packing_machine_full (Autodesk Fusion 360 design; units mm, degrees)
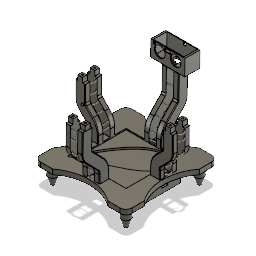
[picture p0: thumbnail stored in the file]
sketch "Sketch1" plane through (0, 0, 0) normal (0, 1, 0) x axis (1, 0, 0)
  line L1 (31.4678, 7.6066) -> (-53.5322, 7.6066)
  line L2 (-53.5322, -77.3934) -> (31.4678, -77.3934)
  line L3 (-53.5322, 7.6066) -> (-53.5322, -77.3934)
  line L4 (-24.0269, 7.6066) -> (-16.0269, 7.6066)
  line L5 (-24.0269, 23.3155) -> (-24.0269, 7.6066)
  line L6 (-16.0269, 7.6066) -> (-16.0269, 23.3155)
  line L7 (3.9731, 7.6066) -> (-4.0269, 7.6066)
  line L8 (3.9731, 23.3155) -> (3.9731, 7.6066)
  line L9 (-4.0269, 7.6066) -> (-4.0269, 23.3155)
  line L10 (-69.5322, -10.1974) -> (-53.5322, -10.1974)
  line L11 (-53.5322, -18.1974) -> (-69.5322, -18.1974)
  line L12 (-53.5322, -10.1974) -> (-53.5322, -18.1974)
  line L13 (-69.5322, -30.1974) -> (-53.5322, -30.1974)
  line L14 (-53.5322, -38.1974) -> (-69.5322, -38.1974)
  line L15 (-53.5322, -30.1974) -> (-53.5322, -38.1974)
  line L16 (-24.0269, -93.3934) -> (-24.0269, -77.3934)
  line L17 (-16.0269, -93.3934) -> (-16.0269, -77.3934)
  line L18 (-4.0269, -93.3934) -> (-4.0269, -77.3934)
  line L19 (3.9731, -93.3934) -> (3.9731, -77.3934)
  line L20 (31.4678, -77.3934) -> (31.4678, 7.6066)
  line L21 (47.4678, -18.1974) -> (31.4678, -18.1974)
  line L22 (47.4678, -10.1974) -> (31.4678, -10.1974)
  line L23 (47.4678, -30.1974) -> (31.4678, -30.1974)
  line L24 (47.4678, -38.1974) -> (31.4678, -38.1974)
  line L25 (-59.6337, -72.3934) -> (-62.6337, -72.3934)
  line L26 (37.4678, -72.3934) -> (40.4678, -72.3934)
  line L27 (-59.6337, 2.6066) -> (-62.6337, 2.6066)
  line L28 (37.4678, 2.6066) -> (40.4678, 2.6066)
  line L29 (-59.6337, -72.3934) -> (-59.6337, 2.6066)
  line L30 (37.4678, 2.6066) -> (37.4678, -72.3934)
  line L31 (-62.6337, -72.3934) -> (-62.6337, 2.6066)
  line L32 (40.4678, -72.3934) -> (40.4678, 2.6066)
  line L33 (-69.5322, -18.1974) -> (-69.5322, -10.1974)
  line L34 (-69.5322, -38.1974) -> (-69.5322, -30.1974)
  line L35 (47.4678, -18.1974) -> (47.4678, -10.1974)
  line L36 (47.4678, -38.1974) -> (47.4678, -30.1974)
  line L37 (-16.0269, -93.3934) -> (-24.0269, -93.3934)
  line L38 (3.9731, -93.3934) -> (-4.0269, -93.3934)
  line L39 (-4.0269, 23.3155) -> (3.9731, 23.3155)
  line L40 (-24.0269, 23.3155) -> (-16.0269, 23.3155)
  line L41 (-5, -80) -> (-15, -80)
  line L42 (-5, -85) -> (-5, -80)
  line L43 (-15, -85) -> (-5, -85)
  line L44 (-15, -80) -> (-15, -85)
  line L45 (-5, 10) -> (-15, 10)
  line L46 (-5, 15) -> (-5, 10)
  line L47 (-15, 15) -> (-5, 15)
  line L48 (-15, 10) -> (-15, 15)
  line L49 (-64, -19) -> (-69, -19)
  line L50 (-64, -29) -> (-64, -19)
  line L51 (-69, -29) -> (-64, -29)
  line L52 (-69, -19) -> (-69, -29)
  line L53 (46.4751, -19) -> (41.4751, -19)
  line L54 (46.4751, -29) -> (46.4751, -19)
  line L55 (41.4751, -29) -> (46.4751, -29)
  line L56 (41.4751, -19) -> (41.4751, -29)
  line L57 (63.9678, 9.8155) -> (63.9678, 30.1039)
  line L58 (-86.0322, -99.8934) -> (-86.0322, -79.8934)
  line L59 (63.9678, -79.8934) -> (63.9678, -99.8934)
  line L60 (53.9678, -109.8934) -> (33.9678, -109.8934)
  line L61 (-76.0322, -109.8934) -> (-56.0322, -109.8934)
  line L62 (-86.0322, 10.1066) -> (-86.0322, 30.1026)
  line L63 (53.9691, 40.1039) -> (33.9678, 40.1066)
  line L64 (-76.0322, 40.1026) -> (-56.0322, 40.1026)
  curve K1 (-62.3587, -78.4407) -> (-62.3587, -78.4407)
  circle C1 centre (48.9678, 24.8155) radius 7.5
  circle C2 centre (-71.0322, 25.1066) radius 7.5
  circle C3 centre (-71.0322, -94.8934) radius 7.5
  circle C4 centre (48.9678, -94.8934) radius 7.5
  arc A1 centre (-11.0349, 100.0947) radius 74.9921 clockwise from (33.9678, 40.1066) to (-56.0322, 40.1026)
  arc A2 centre (123.5319, -35.039) radius 74.5641 clockwise from (63.9678, -79.8934) to (63.9678, 9.8155)
  arc A3 centre (-11.0322, -169.8934) radius 75 clockwise from (-56.0322, -109.8934) to (33.9678, -109.8934)
  arc A4 centre (-146.0322, -34.8934) radius 75 clockwise from (-86.0322, 10.1066) to (-86.0322, -79.8934)
  arc A5 centre (-76.0322, 30.1026) radius 10 clockwise from (-86.0322, 30.1026) to (-76.0322, 40.1026)
  arc A6 centre (53.9678, 30.1039) radius 10 clockwise from (53.9691, 40.1039) to (63.9678, 30.1039)
  arc A7 centre (53.9678, -99.8934) radius 10 clockwise from (63.9678, -99.8934) to (53.9678, -109.8934)
  arc A8 centre (-76.0322, -99.8934) radius 10 clockwise from (-76.0322, -109.8934) to (-86.0322, -99.8934)
  point P4 (-53.5322, -77.3934)
  point P5 (-53.5322, 7.6066)
  point P28 (-62.6337, -72.3934)
  point P29 (-59.6337, -72.3934)
  point P30 (40.4678, -72.3934)
  point P31 (37.4678, -72.3934)
  point P32 (-62.6337, 2.6066)
  point P33 (-59.6337, 2.6066)
  point P34 (40.4678, 2.6066)
  point P35 (37.4678, 2.6066)
  point P52 (-15, -80)
  point P53 (-5, -80)
  point P55 (-15, -85)
  point P56 (-15, 10)
  point P57 (-5, 10)
  point P59 (-15, 15)
  point P60 (-69, -19)
  point P61 (-64, -19)
  point P63 (-69, -29)
  point P64 (41.4751, -19)
  point P65 (46.4751, -19)
  point P67 (41.4751, -29)
  dimension "d121" diameter C1 = 15
  dimension "d124" diameter C2 = 15
  dimension "d127" diameter C3 = 15
  dimension "d130" diameter C4 = 15
  dimension "d162" distance P4 P5 = 85
  dimension "d167" distance L6 L9 = 12
  dimension "d169" distance L11 L13 = 12
  dimension "d179" distance P28 P29 = 3
  dimension "d181" distance P30 P31 = 3
  dimension "d183" distance P32 P33 = 3
  dimension "d186" distance P34 P35 = 3
  dimension "d188" distance L2 L25 = 5
  dimension "d189" distance L2 L26 = 5
  dimension "d192" distance L1 L28 = 5
  dimension "d193" distance L1 L27 = 5
  dimension "d407" distance P52 P53 = 10
  dimension "d408" distance P52 P55 = 5
  dimension "d409" distance P56 P57 = 10
  dimension "d410" distance P56 P59 = 5
  dimension "d411" distance P60 P61 = 5
  dimension "d412" distance P60 P63 = 10
  dimension "d413" distance P64 P65 = 5
  dimension "d414" distance P64 P67 = 10
  dimension "d502" radius A5 = 10
extrude "Extrude26" new body sketch "Sketch1" profile of L3 L25 L29 K1 along normal blind 3
extrude "Extrude9" new body sketch "Sketch1" profile of C1 C2 C3 C4 against normal blind 15
extrude "Extrude2" new body sketch "Sketch1" profile of L1 L2 L3 L4 L7 L12 L15 L20 K1 along normal blind 6
extrude "Extrude1" new body sketch "Sketch1" profile of L1 L2 L3 L4 L5 L6 L7 L8 L9 L10 L11 L12 L13 L14 L15 C1 C2 C3 C4 L16 L17 L18 L19 L20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 along normal blind 8
sketch "Sketch3" plane through (0, 0, 0) normal (1, 0, 0) x axis (0, 0, -1)
  line L1 (-77.6845, 0) -> (-89.6845, 0)
  line L2 (-81.7624, 30.5676) -> (-81.7624, 0.5676)
  line L3 (-109.6726, 59.221) -> (-81.7624, 30.5676)
  line L4 (-109.0151, 94.2149) -> (-109.6726, 59.221)
  line L5 (23.3155, 0) -> (7.6066, 0)
  line L6 (10, 30.5) -> (10, 0.5)
  line L7 (37.7935, 59.2667) -> (10, 30.5)
  line L8 (38.6405, 99.2577) -> (37.7935, 59.2667)
  point P4 (-81.7624, 0.5676)
  point P5 (-81.7624, 30.5676)
  point P6 (-109.6726, 59.221)
  point P7 (-109.0151, 94.2149)
  point P10 (10, 0.5)
  point P11 (10, 30.5)
  point P12 (37.7935, 59.2667)
  point P13 (38.6405, 99.2577)
  dimension "d21" distance P4 P5 = 30
  dimension "d23" distance P5 P6 = 40
  dimension "d24" distance P6 P7 = 35
  dimension "d26" distance P10 P11 = 30
  dimension "d28" distance P11 P12 = 40
  dimension "d29" distance P12 P13 = 40
sweep "Sweep2" sketch "Sketch1" TwistAngle 0 TaperAngle 0
sweep "Sweep1" sketch "Sketch1" TwistAngle 0 TaperAngle 0
sketch "Sketch4"
  line L1 (31.4678, 0) -> (43.352, 0)
  line L2 (34, 31) -> (34, 1)
  line L3 (55.2132, 52.2132) -> (34, 31)
  line L4 (55.2132, 82.2132) -> (55.2132, 52.2132)
  line L5 (-56.9466, 31) -> (-56.9466, 1)
  line L6 (-78.1598, 52.2132) -> (-56.9466, 31)
  line L7 (-78.1598, 82.2132) -> (-78.1598, 52.2132)
  point P4 (34, 1)
  point P5 (34, 31)
  point P6 (55.2132, 52.2132)
  point P7 (55.2132, 82.2132)
  point P10 (-78.1598, 52.2132)
  point P11 (-78.1598, 82.2132)
  dimension "d42" distance P4 P5 = 30
  dimension "d44" distance P5 P6 = 30
  dimension "d45" distance P6 P7 = 30
  dimension "d415" distance P10 P11 = 30
sweep "Sweep3" sketch "Sketch1" TwistAngle 0 TaperAngle 0
sweep "Sweep4" sketch "Sketch1" TwistAngle 0 TaperAngle 0
fillet "Fillet1" radius 1
work_plane "WorkPlane1" AlongDistance 15
sketch "Sketch8" plane through (-71.0322, -30, -24.8155) normal (0, -1, 0) x axis (1, 0, 0)
  circle C1 centre (0, 0) radius 2.5
  dimension "d136" diameter C1 = 5
loft "Loft1" sketch "Sketch8"
work_plane "WorkPlane2" AlongDistance 15
sketch "Sketch9" plane through (-71.0322, -30, 95.1845) normal (0, -1, 0) x axis (1, 0, 0)
  circle C1 centre (0, 0) radius 2.5
  dimension "d138" diameter C1 = 5
loft "Loft2" sketch "Sketch9"
work_plane "WorkPlane3" AlongDistance 15
sketch "Sketch10" plane through (48.9678, -30, -24.8155) normal (0, -1, 0) x axis (1, 0, 0)
  circle C1 centre (0, 0) radius 2.5
  dimension "d140" diameter C1 = 5
loft "Loft3" sketch "Sketch10"
work_plane "WorkPlane4" AlongDistance 15
sketch "Sketch11" plane through (48.9678, -30, 95.1845) normal (0, -1, 0) x axis (1, 0, 0)
  circle C1 centre (0, 0) radius 2.5
  dimension "d142" diameter C1 = 5
loft "Loft4" sketch "Sketch11"
fillet "Fillet5" radius 3
sketch "Sketch12" plane through (0, 0, 18.1974) normal (0, 0, 1) x axis (1, 0, 0)
  line L1 (-53.5322, 0) -> (-69.5322, 0)
  line L2 (-90.7454, 82.2132) -> (-74.7454, 82.2132)
  line L3 (-53.5322, 32.4143) -> (-53.5322, 0)
  line L4 (-74.7454, 53.6275) -> (-53.5322, 32.4143)
  line L5 (-74.7454, 82.2132) -> (-74.7454, 53.6275)
  line L6 (-90.7454, 47.0001) -> (-90.7454, 82.2132)
  line L7 (-69.5322, 25.7869) -> (-90.7454, 47.0001)
  line L8 (-69.5322, 0) -> (-69.5322, 25.7869)
extrude "Extrude10" add of existing geometry blind 5
sketch "Sketch13" plane through (0, 0, 0) normal (0, 1, 0) x axis (1, 0, 0)
extrude "Extrude11" add sketch "Sketch1" profile of L25 L26 L27 L28 against normal blind 20
sketch "Sketch18" plane through (0, 0, 18.1974) normal (0, 0, 1) x axis (1, 0, 0)
  line L1 (-90.7454, 47.0001) -> (-90.7454, 82.2132)
  line L2 (68.681, 47.0001) -> (68.681, 92.2132)
  circle C1 centre (-89.7454, 79) radius 1
  circle C2 centre (-75.7454, 79) radius 1
  circle C3 centre (-89.7454, 63.5) radius 1
  circle C4 centre (-75.7454, 63.5) radius 1
  circle C5 centre (-87.8667, 48.3965) radius 1
  circle C6 centre (-73.032, 49.7524) radius 1
  circle C7 centre (-65.5074, 41.1094) radius 1
  circle C8 centre (-56.2089, 29.9048) radius 1
  circle C9 centre (-54.7124, 23.0048) radius 1
  circle C10 centre (-54.765, 11.5923) radius 1
  circle C11 centre (-68.3402, 11.4595) radius 1
  circle C12 centre (-68, 23) radius 1
  circle C13 centre (-70, 29) radius 1
  circle C14 centre (-81, 40) radius 1
  circle C15 centre (-89.7454, 79) radius 1
  circle C16 centre (-75.7454, 79) radius 1
  circle C17 centre (-89.7454, 63.5) radius 1
  circle C18 centre (-75.7454, 63.5) radius 1
  circle C19 centre (-81, 40) radius 1
  circle C20 centre (-87.8667, 48.3965) radius 1
  circle C21 centre (-70, 29) radius 1
  circle C22 centre (-68, 23) radius 1
  circle C23 centre (-54.7124, 23.0048) radius 1
  circle C24 centre (-56.2089, 29.9048) radius 1
  circle C25 centre (-65.5074, 41.1094) radius 1
  circle C26 centre (-68.3402, 11.4595) radius 1
  circle C27 centre (-54.765, 11.5923) radius 1
  circle C28 centre (67.681, 69.5) radius 1
  circle C29 centre (53.681, 79) radius 1
  circle C30 centre (53.681, 69.5) radius 1
  circle C31 centre (53.681, 69.5) radius 1
  circle C32 centre (67.681, 69.5) radius 1
  circle C33 centre (67.681, 79) radius 1
  circle C34 centre (46.2758, 11.4595) radius 1
  circle C35 centre (46.2758, 11.4595) radius 1
  circle C36 centre (32.7006, 11.5923) radius 1
  circle C37 centre (32.7006, 11.5923) radius 1
  circle C38 centre (34.1444, 29.9048) radius 1
  circle C39 centre (43.4429, 41.1094) radius 1
  circle C40 centre (43.4429, 41.1094) radius 1
  circle C41 centre (47.9356, 29) radius 1
  circle C42 centre (58.9356, 40) radius 1
  circle C43 centre (47.9356, 29) radius 1
  circle C44 centre (65.8022, 48.3965) radius 1
  circle C45 centre (45.9356, 23) radius 1
  circle C46 centre (65.8022, 48.3965) radius 1
  circle C47 centre (32.648, 23.0048) radius 1
  circle C48 centre (50.9676, 49.7524) radius 1
  circle C49 centre (32.648, 23.0048) radius 1
  circle C50 centre (34.1444, 29.9048) radius 1
  circle C51 centre (67.681, 79) radius 1
  circle C52 centre (45.9356, 23) radius 1
  circle C53 centre (58.9356, 40) radius 1
  point P4 (-89.7454, 79)
  dimension "d269" diameter C1 = 2
  dimension "d270" distance L1 P4 = 1
  dimension "d275" diameter C7 = 2
  dimension "d276" diameter C8 = 2
  dimension "d277" diameter C9 = 2
  dimension "d278" diameter C10 = 2
  dimension "d279" diameter C14 = 2
  dimension "d280" diameter C13 = 2
  dimension "d281" diameter C12 = 2
  dimension "d282" diameter C11 = 2
  dimension "d305" diameter C15 = 2
  dimension "d306" diameter C25 = 2
  dimension "d307" diameter C24 = 2
  dimension "d308" diameter C23 = 2
  dimension "d309" diameter C27 = 2
  dimension "d310" diameter C19 = 2
  dimension "d311" diameter C21 = 2
  dimension "d312" diameter C22 = 2
  dimension "d313" diameter C26 = 2
sketch "Sketch19" plane through (37.4678, 0, 0) normal (-1, 0, 0) x axis (0, 0, 1)
  line L1 (-2.6066, 0) -> (72.3934, 0)
  line L2 (-2.6066, -20) -> (-2.6066, 0)
  line L3 (72.3934, -20) -> (-2.6066, -20)
  line L4 (72.3934, 0) -> (72.3934, -20)
  line L5 (-2.6066, -20) -> (72.3934, -20)
  line L6 (-2.6066, -17) -> (-2.6066, -20)
  line L7 (72.3934, -17) -> (-2.6066, -17)
  line L8 (72.3934, -20) -> (72.3934, -17)
  line L9 (0.3934, -17) -> (-2.6066, -17)
  line L10 (0.3934, -14) -> (0.3934, -17)
  line L11 (-2.6066, -14) -> (0.3934, -14)
  line L12 (-2.6066, -17) -> (-2.6066, -14)
  point P6 (72.3934, -20)
  point P9 (72.3934, -17)
  point P8 (-2.6066, -17)
  point P12 (-2.6066, -14)
  point P10 (0.3934, -17)
  dimension "d255" distance P6 P9 = 3
  dimension "d258" distance P8 P12 = 3
  dimension "d259" distance P8 P10 = 3
extrude "Extrude18" add sketch "Sketch19" profile of L2 L3 L4 along normal blind 5
sketch "Sketch20" plane through (-59.6337, 0, 0) normal (1, 0, 0) x axis (0, 0, -1)
  line L1 (-72.3934, 0) -> (2.6066, 0)
  line L2 (-72.3934, -20) -> (-72.3934, 0)
  line L3 (2.6066, -20) -> (-72.3934, -20)
  line L4 (2.6066, 0) -> (2.6066, -20)
  line L5 (2.6066, -20) -> (-72.3934, -20)
  line L6 (2.6066, -17) -> (2.6066, -20)
  line L7 (-72.3934, -17) -> (2.6066, -17)
  line L8 (-72.3934, -20) -> (-72.3934, -17)
  line L9 (-0.3934, -17) -> (2.6066, -17)
  line L10 (-0.3934, -14) -> (-0.3934, -17)
  line L11 (2.6066, -14) -> (-0.3934, -14)
  line L12 (2.6066, -17) -> (2.6066, -14)
  point P6 (-72.3934, -20)
  point P7 (2.6066, -20)
  point P9 (-72.3934, -17)
  point P8 (2.6066, -17)
  point P10 (-0.3934, -17)
  point P12 (2.6066, -14)
  dimension "d227" distance P6 P7 = 75
  dimension "d228" distance P6 P9 = 3
  dimension "d229" distance P8 P10 = 3
  dimension "d230" distance P8 P12 = 3
extrude "Extrude19" add sketch "Sketch20" profile of L2 L3 L4 L5 L6 L7 L8 L9 L10 L11 L12 along normal blind 5
combine "Combine1"
fillet "Fillet13" radius 12
fillet "Fillet14" radius 30
fillet "Fillet15" radius 5
fillet "Fillet16" radius 20
sketch "Sketch21" plane through (0, 82.2132, 0) normal (0, 1, 0) x axis (-1, 0, 0)
  line L1 (89.7454, 10.1974) -> (75.7454, 10.1974)
  line L2 (90.7454, 18.1974) -> (90.7454, 11.1974)
  line L3 (74.7454, 18.1974) -> (90.7454, 18.1974)
  line L4 (74.7454, 11.1974) -> (74.7454, 18.1974)
  arc A1 centre (75.7454, 11.1974) radius 1 clockwise from (75.7454, 10.1974) to (74.7454, 11.1974)
  arc A2 centre (89.7454, 11.1974) radius 1 clockwise from (90.7454, 11.1974) to (89.7454, 10.1974)
  arc A3 centre (81.1475, 25.0943) radius 11.819 clockwise from (90.2904, 32.584) to (90.7454, 18.1974)
  arc A4 centre (86.0713, 24.3961) radius 12.9112 clockwise from (74.7454, 18.1974) to (75.5878, 31.9324)
  arc A5 centre (-57.1895, 24.4354) radius 7.6575 clockwise from (-56, 32) to (-52.7483, 18.1974)
  arc A6 centre (-64.8318, 24.7359) radius 7.5808 clockwise from (-68.6681, 18.1974) to (-67, 32)
  arc A7 centre (-54.9641, 24.3467) radius 14.8392 clockwise from (-43.4429, 33.699) to (-43.4429, 14.9945)
sweep "Sweep15" sketch "Sketch18" TwistAngle 0 TaperAngle 0
sweep "Sweep14" sketch "Sketch18" TwistAngle 0 TaperAngle 0
sweep "Sweep13" sketch "Sketch18" TwistAngle 0 TaperAngle 0
sweep "Sweep12" sketch "Sketch18" TwistAngle 0 TaperAngle 0
sweep "Sweep11" sketch "Sketch18" TwistAngle 0 TaperAngle 0
sweep "Sweep10" sketch "Sketch18" TwistAngle 0 TaperAngle 0
sweep "Sweep9" sketch "Sketch18" TwistAngle 0 TaperAngle 0
fillet "Fillet17" radius 1
sweep "Sweep16" sketch "Sketch18" TwistAngle 0 TaperAngle 0
sketch "Sketch22" plane through (-4.0269, 0, 0) normal (-1, 0, 0) x axis (0, 0, 1)
  line L1 (120.6441, 94.4334) -> (121.236, 62.9332)
  line L2 (104.6469, 94.1328) -> (120.6441, 94.4334)
  line L3 (105.2309, 63.0501) -> (104.6469, 94.1328)
  line L4 (85.9034, 41.0803) -> (103.8135, 59.4673)
  line L5 (77.3934, 8) -> (77.3934, 20.1476)
  line L6 (93.3934, 20.9607) -> (93.3934, 8)
  line L7 (115.5662, 48.6023) -> (96.7974, 29.3338)
  line L8 (93.3934, 8) -> (77.3934, 8)
  arc A1 centre (101.2395, 62.5575) radius 20 clockwise from (121.236, 62.9332) to (115.5662, 48.6023)
  arc A2 centre (100.2318, 62.9561) radius 5 clockwise from (105.2309, 63.0501) to (103.8135, 59.4673)
  arc A3 centre (107.3934, 20.1476) radius 30 clockwise from (77.3934, 20.1476) to (85.9034, 41.0803)
  arc A4 centre (105.3934, 20.9607) radius 12 clockwise from (93.3934, 20.9607) to (96.7974, 29.3338)
  circle C1 centre (105.5904, 89.151) radius 1
  circle C2 centre (119.5904, 89.4141) radius 1
  circle C3 centre (106.0037, 75.151) radius 1
  circle C4 centre (78.7934, 23.0298) radius 1
  circle C5 centre (92.3934, 20.942) radius 1
  circle C6 centre (86.6872, 39.7487) radius 1
  circle C7 centre (95.8673, 29.9599) radius 1
  circle C8 centre (96.7767, 50.328) radius 1
  circle C9 centre (92.3934, 9.2738) radius 1
  circle C10 centre (78.3934, 9.2818) radius 1
  circle C11 centre (109.69, 44.3203) radius 1
  circle C12 centre (118.2899, 55.8791) radius 1
  circle C13 centre (119.9812, 76.4843) radius 1
  circle C14 centre (-49.2213, 56.4899) radius 1
  circle C15 centre (-17.853, 39.9535) radius 1
  circle C16 centre (-9.1762, 23.2216) radius 1
  circle C17 centre (-36.9694, 75.8924) radius 1
  circle C18 centre (-50.9373, 96.8082) radius 1
  circle C19 centre (-22.0868, 12.4349) radius 1
  circle C20 centre (-50.4009, 77.3377) radius 1
  circle C21 centre (-8.8349, 11.4043) radius 1
  circle C22 centre (-22.0514, 20.7273) radius 1
  circle C23 centre (-37.285, 97.151) radius 1
  circle C24 centre (-32.5795, 36.8076) radius 1
  circle C25 centre (-28.9723, 52.2127) radius 1
  point P18 (106.0037, 75.151)
  point P30 (119.9812, 76.4843)
  point P24 (78.3934, 9.2818)
  point P21 (92.3934, 9.2738)
  point P20 (92.3934, 20.942)
  point P19 (78.7934, 23.0298)
  dimension "d376" distance L3 P18 = 1
  dimension "d377" distance L1 P30 = 1
  dimension "d379" distance L5 P24 = 1
  dimension "d380" distance L6 P21 = 1
  dimension "d381" distance L6 P20 = 1
  dimension "d382" distance L5 P19 = 1.4
sketch "Sketch23" plane through (0, 92.1339, -1.7312) normal (0, 0.9998, -0.0188) x axis (-1, 0, 0)
  line L1 (-3.9731, 107.3969) -> (-3.9731, 121.3969)
  line L2 (4.0269, 106.3969) -> (-2.9731, 106.3969)
  line L3 (4.0269, 122.3969) -> (4.0269, 106.3969)
  line L4 (-2.9731, 122.3969) -> (4.0269, 122.3969)
  line L5 (16.0269, 106.3969) -> (23.0269, 106.3969)
  line L6 (23.0269, 122.3969) -> (16.0269, 122.3969)
  line L7 (-2.9731, -34.3755) -> (4.0269, -34.3755)
  line L8 (16.0269, -49.9951) -> (23.0269, -49.9951)
  line L9 (4.0269, -50.0844) -> (-2.9731, -50.0844)
  arc A1 centre (-2.9731, 121.3969) radius 1 clockwise from (-3.9731, 121.3969) to (-2.9731, 122.3969)
  arc A2 centre (-2.9731, 107.3969) radius 1 clockwise from (-2.9731, 106.3969) to (-3.9731, 107.3969)
  arc A3 centre (10.0269, 114.4613) radius 12.4613 clockwise from (19.5269, 106.3969) to (0.5269, 106.3969)
  arc A4 centre (10.0269, 112.946) radius 13.4004 clockwise from (0.5269, 122.3969) to (19.5269, 122.3969)
  arc A5 centre (10.0194, -62.55) radius 29.903 clockwise from (0, -34.3755) to (20.0387, -34.3755)
  arc A6 centre (9.908, -24.72) radius 27.0436 clockwise from (19.5269, -49.9951) to (0.5269, -50.0844)
sweep "Sweep19" sketch "Sketch22" TwistAngle 0 TaperAngle 0
sweep "Sweep20" sketch "Sketch22" TwistAngle 0 TaperAngle 0
sweep "Sweep18" sketch "Sketch22" TwistAngle 0 TaperAngle 0
sweep "Sweep17" sketch "Sketch22" TwistAngle 0 TaperAngle 0
sketch "Sketch24" plane through (0, 8, 0) normal (0, 1, 0) x axis (-1, 0, 0)
  line L1 (68.5322, 38.1974) -> (54.5322, 38.1974)
  line L2 (69.5322, 30.1974) -> (69.5322, 37.1974)
  line L3 (69.5322, 11.1974) -> (69.5322, 18.1974)
  line L4 (54.5322, 10.1974) -> (68.5322, 10.1974)
  line L5 (53.5322, 37.1974) -> (53.5322, 55.8709)
  line L6 (76.0322, -40.1026) -> (56.0322, -40.1026)
  line L7 (86.0322, -10.1066) -> (86.0322, -30.1026)
  line L8 (86.0322, 99.8934) -> (86.0322, 79.8934)
  line L9 (56.0322, 109.8934) -> (76.0322, 109.8934)
  line L10 (-53.9678, 109.8934) -> (-33.9678, 109.8934)
  line L11 (-63.9678, 79.8934) -> (-63.9678, 99.8934)
  line L12 (-63.9678, -30.1039) -> (-63.9678, -9.8155)
  line L13 (-33.9678, -40.1066) -> (-53.9691, -40.1039)
  line L14 (-41.4751, 19) -> (-41.4751, 29)
  line L15 (-46.4751, 19) -> (-41.4751, 19)
  line L16 (-46.4751, 29) -> (-46.4751, 19)
  line L17 (-41.4751, 29) -> (-46.4751, 29)
  line L18 (69, 19) -> (69, 29)
  line L19 (64, 19) -> (69, 19)
  line L20 (64, 29) -> (64, 19)
  line L21 (69, 29) -> (64, 29)
  line L22 (5, -15) -> (15, -15)
  line L23 (5, -10) -> (5, -15)
  line L24 (15, -10) -> (5, -10)
  line L25 (15, -15) -> (15, -10)
  line L26 (15, 80) -> (15, 85)
  line L27 (5, 80) -> (15, 80)
  line L28 (5, 85) -> (5, 80)
  line L29 (15, 85) -> (5, 85)
  line L30 (16.0269, 93.3934) -> (16.0269, 77.3934)
  line L31 (23.0269, 93.3934) -> (16.0269, 93.3934)
  line L32 (24.0269, 78.3934) -> (24.0269, 92.3934)
  line L33 (53.5322, 77.3934) -> (23.0269, 77.3934)
  line L34 (53.5322, 30.1974) -> (69.5322, 30.1974)
  line L35 (53.5322, 18.1974) -> (53.5322, 30.1974)
  line L36 (69.5322, 18.1974) -> (53.5322, 18.1974)
  line L37 (23.0269, -7.6066) -> (53.5322, -7.6066)
  line L38 (24.0269, -22.3155) -> (24.0269, -8.6066)
  line L39 (16.0269, -23.3155) -> (23.0269, -23.3155)
  line L40 (16.0269, -7.6066) -> (16.0269, -23.3155)
  line L41 (4.0269, -7.6066) -> (16.0269, -7.6066)
  line L42 (4.0269, -23.3155) -> (4.0269, -7.6066)
  line L43 (-3.9731, -23.3155) -> (4.0269, -23.3155)
  line L44 (-3.9731, -8.6066) -> (-3.9731, -23.3155)
  line L45 (-31.4678, -7.6066) -> (-2.9731, -7.6066)
  line L46 (-31.4678, 11.1974) -> (-31.4678, -7.6066)
  line L47 (-46.4678, 10.1974) -> (-32.4678, 10.1974)
  line L48 (-47.4678, 18.1974) -> (-47.4678, 11.1974)
  line L49 (-31.4678, 18.1974) -> (-47.4678, 18.1974)
  line L50 (-31.4678, 30.1974) -> (-31.4678, 18.1974)
  line L51 (-46.4678, 30.1974) -> (-31.4678, 30.1974)
  line L52 (-47.4678, 37.1974) -> (-47.4678, 31.1974)
  line L53 (-32.4678, 38.1974) -> (-46.4678, 38.1974)
  line L54 (-31.4678, 77.3934) -> (-31.4678, 37.1974)
  line L55 (-2.9731, 77.3934) -> (-31.4678, 77.3934)
  line L56 (-3.9731, 92.3934) -> (-3.9731, 78.3934)
  line L57 (4.0269, 93.3934) -> (-2.9731, 93.3934)
  line L58 (4.0269, 77.3934) -> (4.0269, 93.3934)
  line L59 (16.0269, 77.3934) -> (4.0269, 77.3934)
  line L60 (53.5322, 75.8031) -> (53.5322, 77.3934)
  curve K1 (53.5322, 55.8709) -> (53.5322, 75.8031)
  line L61 (53.5322, -7.6066) -> (53.5322, 11.1974)
  arc A1 centre (68.5322, 37.1974) radius 1 clockwise from (68.5322, 38.1974) to (69.5322, 37.1974)
  arc A2 centre (68.5322, 11.1974) radius 1 clockwise from (69.5322, 11.1974) to (68.5322, 10.1974)
  arc A3 centre (54.5322, 11.1974) radius 1 clockwise from (54.5322, 10.1974) to (53.5322, 11.1974)
  arc A4 centre (11.0349, -100.0947) radius 74.9921 clockwise from (-33.9678, -40.1066) to (56.0322, -40.1026)
  arc A5 centre (146.0322, 34.8934) radius 75 clockwise from (86.0322, -10.1066) to (86.0322, 79.8934)
  arc A6 centre (11.0322, 169.8934) radius 75 clockwise from (56.0322, 109.8934) to (-33.9678, 109.8934)
  arc A7 centre (-123.5319, 35.039) radius 74.5641 clockwise from (-63.9678, 79.8934) to (-63.9678, -9.8155)
  arc A8 centre (23.0269, 92.3934) radius 1 clockwise from (23.0269, 93.3934) to (24.0269, 92.3934)
  arc A9 centre (23.0269, 78.3934) radius 1 clockwise from (24.0269, 78.3934) to (23.0269, 77.3934)
  arc A10 centre (23.0269, -8.6066) radius 1 clockwise from (23.0269, -7.6066) to (24.0269, -8.6066)
  arc A11 centre (23.0269, -22.3155) radius 1 clockwise from (24.0269, -22.3155) to (23.0269, -23.3155)
  arc A12 centre (-2.9731, -8.6066) radius 1 clockwise from (-3.9731, -8.6066) to (-2.9731, -7.6066)
  arc A13 centre (-32.4678, 11.1974) radius 1 clockwise from (-31.4678, 11.1974) to (-32.4678, 10.1974)
  arc A14 centre (-46.4678, 11.1974) radius 1 clockwise from (-46.4678, 10.1974) to (-47.4678, 11.1974)
  arc A15 centre (-46.4678, 31.1974) radius 1 clockwise from (-46.4678, 30.1974) to (-47.4678, 31.1974)
  arc A16 centre (-46.4678, 37.1974) radius 1 clockwise from (-47.4678, 37.1974) to (-46.4678, 38.1974)
  arc A17 centre (-32.4678, 37.1974) radius 1 clockwise from (-32.4678, 38.1974) to (-31.4678, 37.1974)
  arc A18 centre (-2.9731, 78.3934) radius 1 clockwise from (-2.9731, 77.3934) to (-3.9731, 78.3934)
  arc A19 centre (-2.9731, 92.3934) radius 1 clockwise from (-3.9731, 92.3934) to (-2.9731, 93.3934)
  arc A20 centre (76.0322, 99.8934) radius 10 clockwise from (76.0322, 109.8934) to (86.0322, 99.8934)
  arc A21 centre (-53.9678, 99.8934) radius 10 clockwise from (-63.9678, 99.8934) to (-53.9678, 109.8934)
  arc A22 centre (-53.9678, -30.1039) radius 10 clockwise from (-53.9691, -40.1039) to (-63.9678, -30.1039)
  arc A23 centre (76.0322, -30.1026) radius 10 clockwise from (86.0322, -30.1026) to (76.0322, -40.1026)
  arc A24 centre (54.5322, 37.1974) radius 1 clockwise from (53.5322, 37.1974) to (54.5322, 38.1974)
sketch "Sketch25" plane through (0, 82.2132, 0) normal (0, 1, 0) x axis (-1, 0, 0)
  line L1 (74.7454, 30.1974) -> (74.7454, 37.1974)
  line L2 (90.7454, 30.1974) -> (74.7454, 30.1974)
  line L3 (90.7454, 37.1974) -> (90.7454, 30.1974)
  line L4 (75.7454, 38.1974) -> (89.7454, 38.1974)
  line L5 (89.7454, 10.1974) -> (75.7454, 10.1974)
  line L6 (90.7454, 18.1974) -> (90.7454, 11.1974)
  line L7 (-52.681, 37.1974) -> (-52.681, 30.1974)
  line L8 (-52.681, 18.1974) -> (-52.681, 11.1974)
  line L9 (-53.681, 10.1974) -> (-67.681, 10.1974)
  line L10 (-67.681, 38.1974) -> (-53.681, 38.1974)
  line L11 (-64.681, 30.1974) -> (-56.681, 30.1974)
  line L12 (-64.681, 38.1974) -> (-64.681, 30.1974)
  line L13 (-56.681, 38.1974) -> (-64.681, 38.1974)
  line L14 (-56.681, 30.1974) -> (-56.681, 38.1974)
  line L15 (-52.681, 30.1974) -> (-67.681, 30.1974)
  line L16 (-68.681, 31.1974) -> (-68.681, 37.1974)
  line L17 (-56.8022, 18.1974) -> (-64.8022, 18.1974)
  line L18 (-56.8022, 10.1974) -> (-56.8022, 18.1974)
  line L19 (-64.8022, 10.1974) -> (-56.8022, 10.1974)
  line L20 (-64.8022, 18.1974) -> (-64.8022, 10.1974)
  line L21 (86.7454, 10.1974) -> (78.7454, 10.1974)
  line L22 (86.7454, 18.1974) -> (86.7454, 10.1974)
  line L23 (78.7454, 18.1974) -> (86.7454, 18.1974)
  line L24 (78.7454, 10.1974) -> (78.7454, 18.1974)
  line L25 (74.7454, 11.1974) -> (74.7454, 18.1974)
  line L26 (86.9672, 30.1974) -> (78.9672, 30.1974)
  line L27 (86.9672, 38.1974) -> (86.9672, 30.1974)
  line L28 (78.9672, 38.1974) -> (86.9672, 38.1974)
  line L29 (78.9672, 30.1974) -> (78.9672, 38.1974)
  line L30 (84.8876, 30.1974) -> (73.0469, 30.1974)
  arc A1 centre (75.7454, 37.1974) radius 1 clockwise from (74.7454, 37.1974) to (75.7454, 38.1974)
  arc A2 centre (89.7454, 37.1974) radius 1 clockwise from (89.7454, 38.1974) to (90.7454, 37.1974)
  point P22 (-56.681, 30.1974)
  point P23 (-64.681, 30.1974)
  point P29 (-64.8022, 18.1974)
  point P30 (-56.8022, 18.1974)
  point P34 (78.7454, 10.1974)
  point P35 (86.7454, 10.1974)
  point P40 (78.9672, 30.1974)
  point P41 (86.9672, 30.1974)
  dimension "d432" distance P22 P23 = 8
  dimension "d433" distance L12 L16 = 4
  dimension "d434" distance P29 P30 = 8
  dimension "d435" distance P34 P35 = 8
  dimension "d436" distance L24 L25 = 4
  dimension "d437" distance P40 P41 = 8
extrude "Extrude20" add sketch "Sketch25" profile of L2 L4 L5 L9 L10 L11 L12 L13 L14 L15 L17 L18 L19 L20 L21 L22 L23 L24 L26 L27 L28 L29 L30 distance 8
sketch "Sketch26" plane through (0, 90.2132, 0) normal (0, 1, 0) x axis (-1, 0, 0)
  line L1 (78.7454, 10.1974) -> (78.7454, 18.1974)
  line L2 (86.7454, 10.1974) -> (78.7454, 10.1974)
  line L3 (86.7454, 18.1974) -> (86.7454, 10.1974)
  line L4 (78.7454, 18.1974) -> (86.7454, 18.1974)
  line L5 (86.9672, 30.1974) -> (78.9672, 30.1974)
  line L6 (78.9672, 30.1974) -> (78.9672, 38.1974)
  line L7 (-56.8022, 10.1974) -> (-64.8022, 10.1974)
  line L8 (-64.8022, 10.1974) -> (-64.8022, 18.1974)
  line L9 (-56.681, 30.1974) -> (-64.681, 30.1974)
  line L10 (-64.681, 30.1974) -> (-64.681, 38.1974)
  circle C1 centre (82.7454, 14.1974) radius 1.75
  circle C2 centre (82.9672, 34.1974) radius 1.75
  circle C3 centre (-60.8022, 14.1974) radius 1.75
  circle C4 centre (-60.681, 34.1974) radius 1.75
  point P6 (82.7454, 14.1974)
  point P7 (82.9672, 34.1974)
  point P11 (-60.8022, 14.1974)
  point P12 (-60.681, 34.1974)
  dimension "d440" diameter C2 = 3.5
  dimension "d441" distance L4 P6 = 4
  dimension "d442" distance L3 P6 = 4
  dimension "d443" distance P7 L5 = 4
  dimension "d444" distance P7 L6 = 4
  dimension "d445" diameter C3 = 3.5
  dimension "d446" diameter C4 = 3.5
  dimension "d447" distance P11 L7 = 4
  dimension "d448" distance P11 L8 = 4
  dimension "d449" distance P12 L9 = 4
  dimension "d450" distance P12 L10 = 4
extrude "Extrude21" cut sketch "Sketch26" profile of C1 C2 C3 C4 against normal blind 16
thread "Thread1"
sketch "Sketch28" plane through (0, 92.1339, -1.7312) normal (0, 0.9998, -0.0188) x axis (-1, 0, 0)
  line L1 (16.0269, 122.3969) -> (23.0269, 122.3969)
  line L2 (16.0269, 106.3969) -> (16.0269, 122.3969)
  line L3 (23.0269, 106.3969) -> (16.0269, 106.3969)
  line L4 (24.0269, 121.3969) -> (24.0269, 107.3969)
  line L5 (16.0269, 110.3969) -> (24.0269, 110.3969)
  line L6 (16.0269, 118.3969) -> (16.0269, 110.3969)
  line L7 (24.0269, 118.3969) -> (16.0269, 118.3969)
  line L8 (24.0269, 110.3969) -> (24.0269, 118.3969)
  line L9 (4, 118.3969) -> (-4, 118.3969)
  line L10 (4, 110.3969) -> (4, 118.3969)
  line L11 (-4, 110.3969) -> (4, 110.3969)
  line L12 (-4, 118.3969) -> (-4, 110.3969)
  line L13 (4.0269, 106.3969) -> (-2.9731, 106.3969)
  arc A1 centre (23.0269, 121.3969) radius 1 clockwise from (23.0269, 122.3969) to (24.0269, 121.3969)
  arc A2 centre (23.0269, 107.3969) radius 1 clockwise from (24.0269, 107.3969) to (23.0269, 106.3969)
  point P10 (24.0269, 110.3969)
  point P11 (16.0269, 110.3969)
  point P13 (24.0269, 118.3969)
  point P14 (19.5269, 106.3969)
  point P15 (-4, 118.3969)
  point P18 (-4, 110.3969)
  dimension "d453" distance P10 P11 = 8
  dimension "d454" distance P10 P13 = 8
  dimension "d455" distance L5 P14 = 4
  dimension "d456" distance P15 P18 = 8
  dimension "d457" distance L11 L13 = 4
extrude "Extrude22" add sketch "Sketch28" profile of L2 L4 L5 L6 L7 L8 L9 L10 L11 L12 along normal blind 8
sketch "Sketch29" plane through (0, 100.1325, -1.8815) normal (0, 0.9998, -0.0188) x axis (-1, 0, 0)
  line L1 (16.0269, 118.3969) -> (24.0269, 118.3969)
  line L2 (16.0269, 110.3969) -> (16.0269, 118.3969)
  line L3 (24.0269, 110.3969) -> (16.0269, 110.3969)
  line L4 (24.0269, 118.3969) -> (24.0269, 110.3969)
  line L5 (-4, 118.3969) -> (4, 118.3969)
  line L6 (-3.9731, 107.3969) -> (-3.9731, 121.3969)
  circle C1 centre (20.0269, 114.3969) radius 1.75
  circle C2 centre (0.0269, 114.3969) radius 1.75
  point P6 (20.0269, 114.3969)
  point P7 (0.0269, 114.3969)
  dimension "d460" diameter C1 = 3.5
  dimension "d461" diameter C2 = 3.5
  dimension "d462" distance L1 P6 = 4
  dimension "d463" distance L4 P6 = 4
  dimension "d464" distance P7 L5 = 4
  dimension "d465" distance P7 L6 = 4
extrude "Extrude23" cut sketch "Sketch29" profile of C1 C2 against normal blind 16
sketch "Sketch30" plane through (0, 100.0311, -2.1185) normal (0, 0.9998, -0.0212) x axis (-1, 0, 0)
  line L1 (16.0269, -34.1368) -> (23.0269, -34.1368)
  line L2 (16.0269, -49.8457) -> (16.0269, -34.1368)
  line L3 (23.0269, -49.8457) -> (16.0269, -49.8457)
  line L4 (24.0269, -35.1368) -> (24.0269, -48.8457)
  line L5 (24.0269, -38.1368) -> (16.0269, -38.1368)
  line L6 (24.0269, -46.1368) -> (24.0269, -38.1368)
  line L7 (16.0269, -46.1368) -> (24.0269, -46.1368)
  line L8 (16.0269, -38.1368) -> (16.0269, -46.1368)
  line L9 (4.0269, -38.1368) -> (-3.9731, -38.1368)
  line L10 (4.0269, -46.1368) -> (4.0269, -38.1368)
  line L11 (-3.9731, -46.1368) -> (4.0269, -46.1368)
  line L12 (-3.9731, -38.1368) -> (-3.9731, -46.1368)
  line L13 (-3.9731, -48.8457) -> (-3.9731, -35.1368)
  line L14 (-2.9731, -34.1368) -> (4.0269, -34.1368)
  arc A1 centre (23.0269, -35.1368) radius 1 clockwise from (23.0269, -34.1368) to (24.0269, -35.1368)
  arc A2 centre (23.0269, -48.8457) radius 1 clockwise from (24.0269, -48.8457) to (23.0269, -49.8457)
  point P10 (16.0269, -38.1368)
  point P11 (24.0269, -38.1368)
  point P13 (16.0269, -46.1368)
  point P14 (-3.9731, -38.1368)
  point P17 (-3.9731, -46.1368)
  dimension "d468" distance P10 P11 = 8
  dimension "d469" distance P10 P13 = 8
  dimension "d470" distance L1 L5 = 4
  dimension "d471" distance L3 L7 = 3.7089
  dimension "d472" distance P14 P17 = 8
  dimension "d473" distance L9 L14 = 4
extrude "Extrude24" add sketch "Sketch30" profile of L2 L4 L5 L6 L7 L8 L9 L10 L11 L12 L13 along normal blind 8
sketch "Sketch31" plane through (0, 108.0294, -2.2878) normal (0, 0.9998, -0.0212) x axis (-1, 0, 0)
  line L1 (-3.9731, -46.1368) -> (-3.9731, -38.1368)
  line L2 (4.0269, -46.1368) -> (-3.9731, -46.1368)
  line L3 (4.0269, -38.1368) -> (4.0269, -46.1368)
  line L4 (-3.9731, -38.1368) -> (4.0269, -38.1368)
  line L5 (16.0269, -38.1368) -> (24.0269, -38.1368)
  line L6 (24.0269, -48.8457) -> (24.0269, -35.1368)
  circle C1 centre (0.0269, -42.1368) radius 1.75
  circle C2 centre (20.0269, -42.1368) radius 1.75
  point P6 (0.0269, -42.1368)
  point P7 (20.0269, -42.1368)
  dimension "d476" diameter C1 = 3.5
  dimension "d477" diameter C2 = 3.5
  dimension "d478" distance L4 P6 = 4
  dimension "d479" distance L3 P6 = 4
  dimension "d480" distance P7 L5 = 4
sketch "Sketch32" plane through (0, 108.0294, -2.2878) normal (0, 0.9998, -0.0212) x axis (-1, 0, 0)
  line L1 (24.0269, -46.1368) -> (16.0269, -46.1368)
  line L2 (16.0269, -38.1368) -> (24.0269, -38.1368)
  line L3 (16.0269, -46.1368) -> (16.0269, -38.1368)
  line L4 (38.0269, -29.6368) -> (-17.9731, -29.6368)
  line L5 (38.0269, -54.6368) -> (38.0269, -29.6368)
  line L6 (-17.9731, -54.6368) -> (38.0269, -54.6368)
  line L7 (-17.9731, -29.6368) -> (-17.9731, -54.6368)
  line L8 (4, -49.5956) -> (15.9676, -49.5956)
  line L9 (4, -31) -> (4, -49.5956)
  line L10 (35.0269, -51.6368) -> (35.0269, -31)
  line L11 (-14.9731, -31) -> (-14.9731, -51.6368)
  line L12 (-14.9731, -53.1368) -> (-14.9731, -51.6368)
  line L13 (35.0269, -53.1368) -> (35.0269, -51.6368)
  line L14 (15.9676, -31) -> (15.9676, -49.5956)
  line L15 (35.0269, -53.1368) -> (-14.9731, -53.1368)
  line L16 (35.0269, -31) -> (-14.9731, -31)
  point P6 (-17.9731, -29.6368)
  point P7 (38.0269, -29.6368)
  point P9 (-17.9731, -54.6368)
  dimension "d505" distance P6 P7 = 56
  dimension "d506" distance P6 P9 = 25
  dimension "d514" distance L7 L11 = 3
extrude "Extrude29" new body sketch "Sketch32" profile of L4 L5 L6 L7 L10 L11 L12 L13 L15 along normal blind 23
extrude "Extrude28" add sketch "Sketch32" profile of L4 L5 L6 L7 L8 L9 L10 L11 L12 L13 L14 L15 L16 against normal blind 3
extrude "Extrude25" cut sketch "Sketch31" profile of C1 C2 distance -16
thread "Thread4"
sketch "Sketch33" plane through (0, -0.6275, -29.6301) normal (0, 0.0212, 0.9998) x axis (1, 0, 0)
  line L1 (17.9731, 108.0536) -> (-38.0269, 108.0536)
  line L2 (-5.2741, 129.5536) -> (-5.2741, 124.5536)
  line L3 (-5.2741, 129.5536) -> (-14.777, 129.5536)
  line L4 (-14.777, 129.5536) -> (-14.777, 124.5536)
  line L5 (-5.2741, 124.5536) -> (-14.777, 124.5536)
  line L6 (-30.6225, 129.7149) -> (-33.6225, 129.7149)
  line L7 (11.3775, 126.0536) -> (11.3775, 129.8575)
  line L8 (14.3775, 126.0536) -> (11.3775, 126.0536)
  line L9 (14.3775, 129.8575) -> (14.3775, 126.0536)
  line L10 (-33.6225, 126.0536) -> (-33.6225, 129.7149)
  line L11 (-30.6225, 126.0536) -> (-30.6225, 129.7149)
  line L12 (-33.6225, 126.0536) -> (-30.6225, 126.0536)
  line L13 (17.9731, 131.0536) -> (-38.0269, 131.0536)
  circle C1 centre (-23.0269, 120.0536) radius 8.75
  circle C2 centre (2.9731, 120.0536) radius 8.75
  point P4 (-23.0269, 120.0536)
  point P5 (2.9731, 120.0536)
  point P13 (11.3775, 126.0536)
  point P14 (14.3775, 126.0536)
  dimension "d521" diameter C1 = 17.5
  dimension "d522" diameter C2 = 17.5
  dimension "d525" distance P4 P5 = 26
  dimension "d529" distance P13 P14 = 3
  dimension "d538" distance P4 L13 = 11
  dimension "d541" distance L3 L13 = 1.5
extrude "Extrude31" cut sketch "Sketch33" profile of C1 L2 L3 L4 L5 C2 L6 L7 L8 L9 L10 L11 L12 against normal blind 5
sketch "Sketch34" plane through (0, -1.1568, -54.6245) normal (0, -0.0212, -0.9998) x axis (-1, 0, 0)
  line L1 (38.0269, 131.0536) -> (38.0269, 105.0536)
  line L2 (-17.9731, 131.0536) -> (38.0269, 131.0536)
  line L3 (-17.9731, 105.0536) -> (-17.9731, 131.0536)
  line L4 (8, 130) -> (4, 130)
  line L5 (8, 126) -> (8, 130)
  line L6 (4, 126) -> (8, 126)
  line L7 (4, 130) -> (4, 126)
  line L8 (38.0269, 105.0536) -> (-17.9731, 105.0536)
  point P6 (4, 130)
  point P7 (8, 130)
  point P9 (4, 126)
  dimension "d542" distance P6 P7 = 4
  dimension "d543" distance P6 P9 = 4
extrude "Extrude32" cut sketch "Sketch34" profile of L4 L5 L6 L7 against normal blind 3
sketch "Sketch35" plane through (0, 108.0294, -2.2878) normal (0, 0.9998, -0.0212) x axis (-1, 0, 0)
  line L1 (15.9676, -31) -> (35.0269, -31)
  line L2 (15.9676, -49.5956) -> (15.9676, -31)
  line L3 (4, -49.5956) -> (15.9676, -49.5956)
  line L4 (4, -46.1368) -> (4, -49.5956)
  line L5 (4.0269, -46.1368) -> (4, -46.1368)
  line L6 (4.0269, -38.1368) -> (4.0269, -46.1368)
  line L7 (4, -38.1368) -> (4.0269, -38.1368)
  line L8 (4, -31) -> (4, -38.1368)
  line L9 (-14.9731, -31) -> (4, -31)
  line L10 (-14.9731, -53.1368) -> (-14.9731, -31)
  line L11 (35.0269, -53.1368) -> (-14.9731, -53.1368)
  line L12 (35.0269, -31) -> (35.0269, -53.1368)
  circle C1 centre (0.0269, -42.1368) radius 1.465
  circle C2 centre (20.0269, -42.1368) radius 1.465
sketch "Sketch36" plane through (-62.6337, 0, 0) normal (-1, 0, 0) x axis (0, 0, 1)
  line L1 (-2.6066, 0) -> (72.3934, 0)
  line L2 (-2.6066, -20) -> (-2.6066, 0)
  line L3 (72.3934, -20) -> (-2.6066, -20)
  line L4 (72.3934, 0) -> (72.3934, -20)
  line L5 (28, -2) -> (18, -2)
  line L6 (28, -12) -> (28, -2)
  line L7 (18, -12) -> (28, -12)
  line L8 (18, -2) -> (18, -12)
  point P6 (18, -2)
  point P9 (18, -12)
  point P7 (28, -2)
  dimension "d548" distance P6 P9 = 10
  dimension "d549" distance P6 P7 = 10
extrude "Extrude34" cut sketch "Sketch36" profile of L5 L6 L7 L8 against normal blind 120
fillet "Fillet18" radius 2
fillet "Fillet19" radius 2
fillet "Fillet20" radius 2
extrude "Extrude35" add of existing geometry blind 30
offset_faces "OffsetFaces1" distance 30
